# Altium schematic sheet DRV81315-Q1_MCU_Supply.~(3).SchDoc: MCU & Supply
size 431 x 279 mm; Date: Not shown in title block; ApprovedBy: Not shown in title block; CheckedBy: Not shown in title block; Author: Not shown in title block; CompanyName: Not shown in title block; DrawnBy: Mojtaba Afshar; Engineer: Not shown in title block; Organization: Not shown in title block; Address1: Not shown in title block; Address2: Not shown in title block; Address3: Not shown in title block; Address4: Not shown in title block; DocumentNumber: 1; Revision: Use project parameter SCH_Rev; SheetNumber: 1; SheetTotal: 3; PageSetup: Record=PageOptions¦CenterHorizontal=True¦CenterVertical=True¦PrintScale=1.00¦XCorrection=1.00¦YCorrection=1.00¦PrintKind=0¦BorderSize=5000000¦LeftOffset=0¦BottomOffset=0¦Orientation=2¦PaperLength=1000¦PaperWidth=1000¦Scale=100¦PaperSource=15¦PrintQuality=600¦MediaType=1¦DitherType=10¦PaperKind=Letter¦PrintScaleMode=1
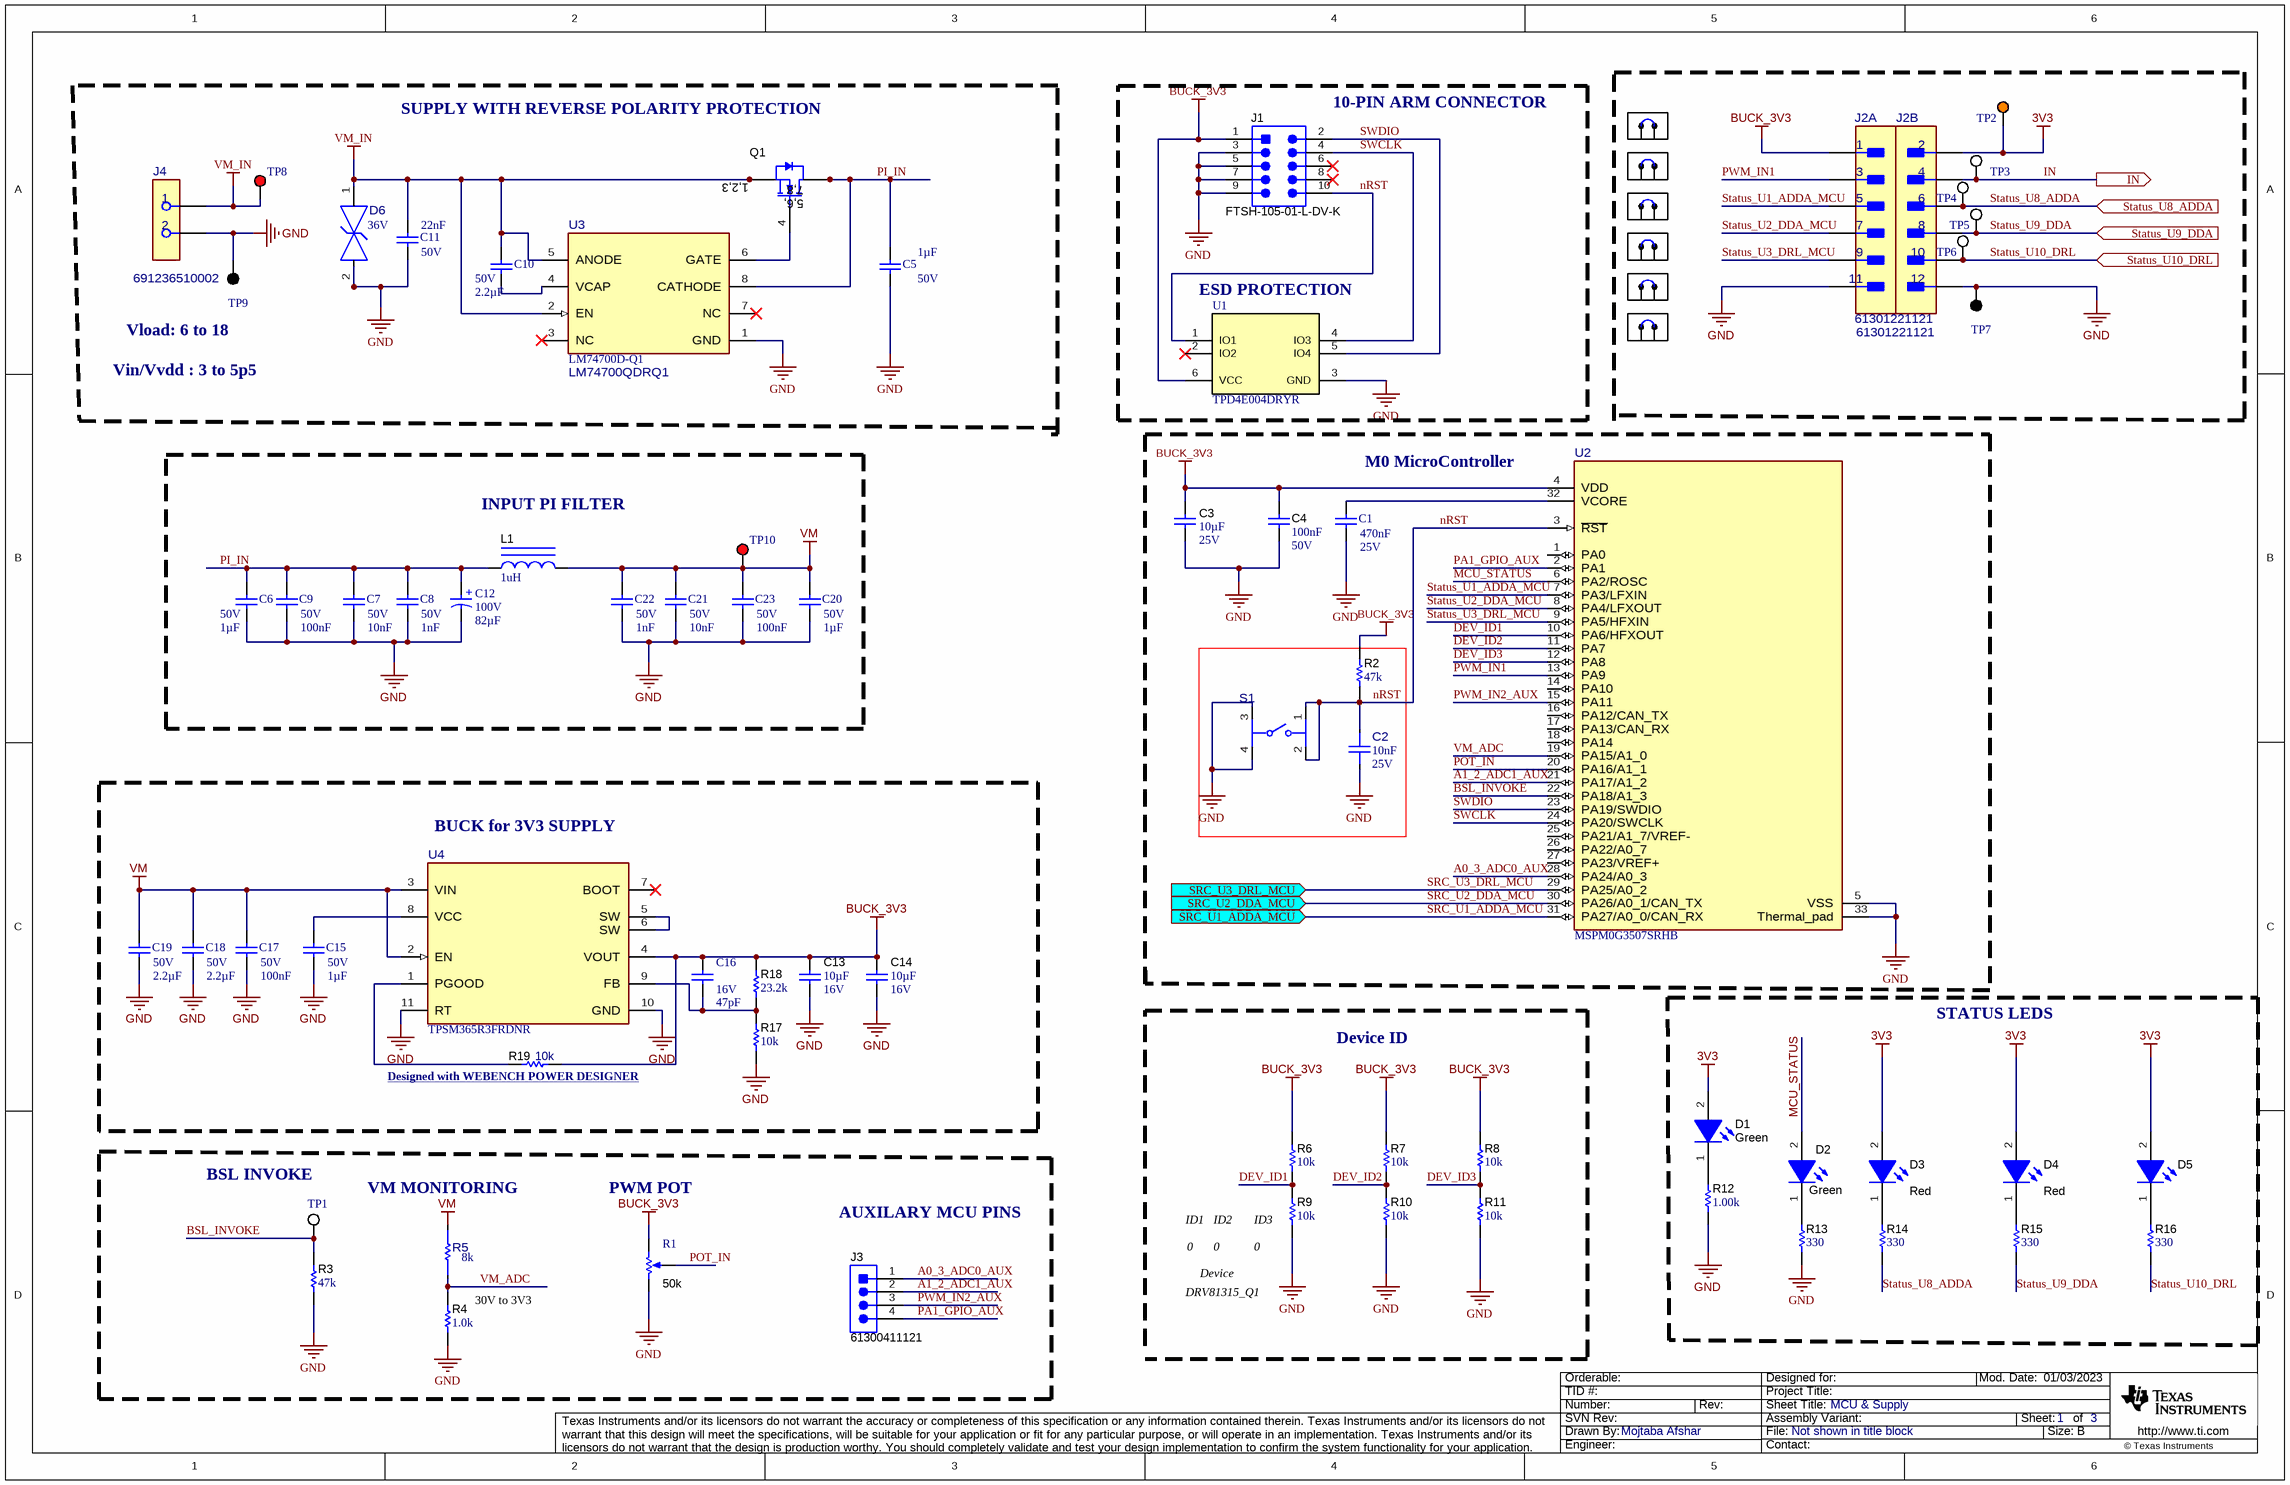
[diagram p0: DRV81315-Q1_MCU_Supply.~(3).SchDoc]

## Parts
C1  value 470nF  Rated Voltage (DC): 25V  [WCAP-CSGP_0603_L1.6W0.8H0.8_Reflow]  (hidden comment: 885012206075R)
C2  Cap_F: 10nF  VDC_V: 25V  [FP-885012206065_0603-MFG]  (hidden comment: 885012206065)
C3  Cap_F: 10µF  VDC_V: 25V  [0603]  (hidden comment: GRM188R61E106KA73D)
C4  Cap_F: 100nF  VDC_V: 50V  [0603]  (hidden comment: 885012206095)
C5  Cap_F: 1µF  Rated Voltage (DC): 50V  [WCAP-CSGP_1206_L3.2W1.6H1.6]  (hidden comment: 885012208093)
C6  Cap_F: 1µF  Rated Voltage (DC): 50V  [WCAP-CSGP_1206_L3.2W1.6H1.6]  (hidden comment: 885012208093)
C7  Cap_F: 10nF  Rated Voltage (DC): 50V  [WCAP-CSGP_0402_L1W0.5H0.5]  (hidden comment: 885012205067)
C8  Cap_F: 1nF  Rated Voltage (DC): 50V  [WCAP-CSGP_0402_L1W0.5H0.5]  (hidden comment: 885012205061)
C9  Cap_F: 100nF  Rated Voltage (DC): 50V  [WCAP-CSGP_0603_L1.6W0.8H0.8_Reflow]  (hidden comment: 885012206095)
C10  Cap_F: 2.2µF  Rated Voltage (DC): 50V  [WCAP-CSGP_1812_L4.5W3.2H2.5]  (hidden comment: 885012210032)
C11  Cap_F: 22nF  Rated Voltage (DC): 50V  [WCAP-CSGP_0603_L1.6W0.8H0.8_Reflow]  (hidden comment: 885012206091)
C12  Cap_F: 82µF  Rated Voltage (DC): 100V  [WCAP-ATUL_D10H20]  (hidden comment: 860040875004)
C13  VDC_V: 16V  ValueDisplayed: 10µF  [0805_150]  (hidden comment: 885012107014)
C14  VDC_V: 16V  ValueDisplayed: 10µF  [0805_150]  (hidden comment: 885012107014)
C15  Cap_F: 1µF  Rated Voltage (DC): 50V  [WCAP-CSGP_1206_L3.2W1.6H1.6]  (hidden comment: 885012208093)
C16  Rated Voltage (DC): 16V  Cap_F: 47pF  [WCAP-CSGP_0402_L1W0.5H0.5]  (hidden comment: 885012005029)
C17  Cap_F: 100nF  Rated Voltage (DC): 50V  [WCAP-CSGP_0603_L1.6W0.8H0.8_Reflow]  (hidden comment: 885012206095)
C18  Cap_F: 2.2µF  Rated Voltage (DC): 50V  [WCAP-CSGP_1812_L4.5W3.2H2.5]  (hidden comment: 885012210032)
C19  Cap_F: 2.2µF  Rated Voltage (DC): 50V  [WCAP-CSGP_1812_L4.5W3.2H2.5]  (hidden comment: 885012210032)
C20  Cap_F: 1µF  Rated Voltage (DC): 50V  [WCAP-CSGP_1206_L3.2W1.6H1.6]  (hidden comment: 885012208093)
C21  Cap_F: 10nF  Rated Voltage (DC): 50V  [WCAP-CSGP_0402_L1W0.5H0.5]  (hidden comment: 885012205067)
C22  Cap_F: 1nF  Rated Voltage (DC): 50V  [WCAP-CSGP_0402_L1W0.5H0.5]  (hidden comment: 885012205061)
C23  Cap_F: 100nF  Rated Voltage (DC): 50V  [WCAP-CSGP_0603_L1.6W0.8H0.8_Reflow]  (hidden comment: 885012206095)
D1  value Green  [WL-SMCW_GREEN]  (hidden comment: 150060VS75000)
D2  value Green  [WL-SMCW_GREEN]  (hidden comment: 150060VS75000)
D3  value Red  [WL-SMCW_RED]  (hidden comment: 150060RS75000)
D4  value Red  [WL-SMCW_RED]  (hidden comment: 150060RS75000)
D5  150060RS75000  [WL-SMCW_RED]  (value not drawn)
D6  VRWM: 36V  [FP-SMBJ36CA-13-F_SMB-MFG]  (hidden comment: SMBJ36CA-13-F)
J1  FTSH-105-01-L-DV-K  [Samtec_FTSH-105-01-x-DV-K]
J2  61301221121  [FP-61301221121_HDR12-MFG]  (parts A,B of 2)
J3  61300411121  [WURTH_61300411121]
J4  691236510002  [FP-691236510002_HHR2-MFG]
L1  ValueDisplayed: 1uH  [WE-LHMI_1335]  (hidden comment: 74437377010)
Q1  CSD19502Q5B  [DNK0008A]  (value not drawn)
R1  value 50k  [Bourns_3352T]  (hidden comment: 3352T-1-503LF)
R2  ValueDisplayed: 47k  [0402]  (hidden comment: CRCW040247K0JNED)
R3  ValueDisplayed: 47k  [0402]  (hidden comment: CRCW040247K0JNED)
R4  ValueDisplayed: 1.0k  [0603]  (hidden comment: RC0603JR-071KL)
R5  value 8k  [FP-RT0603BRE078KL_0603-MFG]  (hidden comment: RT0603BRE078KL)
R6  ValueDisplayed: 10k  [0603L]  (hidden comment: RC0603JR-0710KL)
R7  ValueDisplayed: 10k  [0603L]  (hidden comment: RC0603JR-0710KL)
R8  ValueDisplayed: 10k  [0603L]  (hidden comment: RC0603JR-0710KL)
R9  ValueDisplayed: 10k  [0603L]  (hidden comment: RC0603JR-0710KL)
R10  ValueDisplayed: 10k  [0603L]  (hidden comment: RC0603JR-0710KL)
R11  ValueDisplayed: 10k  [0603L]  (hidden comment: RC0603JR-0710KL)
R12  ValueDisplayed: 1.00k  [0603]  (hidden comment: RC0603FR-071KL)
R13  ValueDisplayed: 330  [0603]  (hidden comment: RC0603JR-07330RL)
R14  ValueDisplayed: 330  [0603]  (hidden comment: RC0603JR-07330RL)
R15  ValueDisplayed: 330  [0603]  (hidden comment: RC0603JR-07330RL)
R16  ValueDisplayed: 330  [0603]  (hidden comment: RC0603JR-07330RL)
R17  ValueDisplayed: 10k  [0603L]  (hidden comment: RC0603JR-0710KL)
R18  ValueDisplayed: 23.2k  [0603]  (hidden comment: RC0603FR-0723K2L)
R19  ValueDisplayed: 10k  [0603L]  (hidden comment: RC0603JR-0710KL)
S1  430481025816  [FP-430481025816_SMT_SW_6MM2_6MM2-MFG]  (value not drawn)
SH1-J2  60900213421  [Wurth_60900213421]  (value not drawn)
SH2-J2  60900213421  [Wurth_60900213421]  (value not drawn)
SH3-J2  60900213421  [Wurth_60900213421]  (value not drawn)
SH4-J2  60900213421  [Wurth_60900213421]  (value not drawn)
SH5-J2  60900213421  [Wurth_60900213421]  (value not drawn)
SH6-J2  60900213421  [Wurth_60900213421]  (value not drawn)
TP1  5002  [Keystone5002]  (value not drawn)
TP2  5013  [Keystone5013]  (value not drawn)
TP3  5012  [Keystone5012]  (value not drawn)
TP4  5012  [Keystone5012]  (value not drawn)
TP5  5012  [Keystone5012]  (value not drawn)
TP6  5012  [Keystone5012]  (value not drawn)
TP7  5011  [Keystone5011]  (value not drawn)
TP8  5010  [Keystone5010]  (value not drawn)
TP9  5011  [Keystone5011]  (value not drawn)
TP10  5010  [Keystone5010]  (value not drawn)
U1  TPD4E004DRYR  [DRY0006A]
U2  MSPM0G3507SRHB  [RHB0032E-MFG]
U3  LM74700QDRQ1  PartNumber: LM74700D-Q1  [D0008A-MFG]
U4  TPSM365R3FRDNR  [RDN0011A-MFG]

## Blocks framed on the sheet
INPUT PI FILTER: C6-C9 C12 C20-C23 L1 TP10
BUCK for 3V3 SUPPLY: C13-C19 R17-R19 U4
STATUS LEDS: D1-D5 R12-R16

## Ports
IN (out), SRC_U1_ADDA_MCU (in), SRC_U2_DDA_MCU (in), SRC_U3_DRL_MCU (in), Status_U8_ADDA (in), Status_U9_DDA (in), Status_U10_DRL (in)

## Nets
3V3: D1.2(A) D3.2(A) D4.2(A) D5.2(A) J2.2 TP2.1
BUCK_3V3: C3.1 C4.1 C13.1 C14.1 C16.2 J1.1 J2.1 R1.1(CCW) R2.2 R6.1 R7.1 R8.1 R18.2 R19.2 U1.6(VCC) U2.4(VDD) U4.4(VOUT)
GND: C1.1 C2.2 C3.2 C4.2 C5.1 C6.1 C7.1 C8.1 C9.1 C11.1 C12.2(N) C13.2 C14.2 C15.1 C17.1 C18.1 C19.1 C20.1 C21.1 C22.1 C23.1 D6.2 J1.3 J1.5 J1.7 J1.9 J2.11 J2.12 J4.2 R1.3(CW) R3.1 R4.1 R9.2 R10.2 R11.2 R12.1 R13.1 R17.1 S1.3 S1.4 TP7.1 TP9.1 U1.3(GND) U2.5(VSS) U2.33(Thermal_pad) U3.1(GND) U4.10(GND) U4.11(RT)
VM: C17.2 C18.2 C19.2 C20.2 C21.2 C22.2 C23.2 L1.2 R5.2 TP10.1 U4.2(EN) U4.3(VIN)
VM_IN: C10.2 C11.2 D6.1 J4.1 Q1.1(S) Q1.2(S) Q1.3(S) TP8.1 U3.2(EN) U3.5(ANODE)
A0_3_ADC0_AUX: J3.1 U2.28(PA24/A0_3)
A1_2_ADC1_AUX: J3.2 U2.21(PA17/A1_2)
BSL_INVOKE: R3.2 TP1.1 U2.22(PA18/A1_3)
DEV_ID1: R6.2 R9.1 U2.10(PA6/HFXOUT)
DEV_ID2: R7.2 R10.1 U2.11(PA7)
DEV_ID3: R8.2 R11.1 U2.12(PA8)
IN: J2.4 TP3.1 ; port IN
MCU_STATUS: D2.2(A) U2.6(PA2/ROSC)
nRST: C2.1 J1.10 R2.1 S1.1 S1.2 U1.1(IO1) U2.3(~{RST})
PA1_GPIO_AUX: J3.4 U2.2(PA1)
PI_IN: C5.2 C6.2 C7.2 C8.2 C9.2 C12.1(P) L1.1 Q1.5(D) Q1.6(D) Q1.7(D) Q1.8(D) Q1.9(D) U3.8(CATHODE)
POT_IN: R1.2(WIPER) U2.20(PA16/A1_1)
PWM_IN1: J2.3 U2.13(PA9)
PWM_IN2_AUX: J3.3 U2.15(PA11)
SRC_U1_ADDA_MCU: U2.31(PA27/A0_0/CAN_RX) ; port SRC_U1_ADDA_MCU
SRC_U2_DDA_MCU: U2.30(PA26/A0_1/CAN_TX) ; port SRC_U2_DDA_MCU
SRC_U3_DRL_MCU: U2.29(PA25/A0_2) ; port SRC_U3_DRL_MCU
Status_U1_ADDA_MCU: J2.5 U2.7(PA3/LFXIN)
Status_U2_DDA_MCU: J2.7 U2.8(PA4/LFXOUT)
Status_U3_DRL_MCU: J2.9 U2.9(PA5/HFXIN)
Status_U8_ADDA: J2.6 R14.1 TP4.1 ; port Status_U8_ADDA
Status_U9_DDA: J2.8 R15.1 TP5.1 ; port Status_U9_DDA
Status_U10_DRL: J2.10 R16.1 TP6.1 ; port Status_U10_DRL
SWCLK: J1.4 U1.4(IO3) U2.24(PA20/SWCLK)
SWDIO: J1.2 U1.5(IO4) U2.23(PA19/SWDIO)
VM_ADC: R4.2 R5.1 U2.19(PA15/A1_0)
NetC1_2: C1.2 U2.32(VCORE)
NetC10_1: C10.1 U3.4(VCAP)
NetC15_2: C15.2 U4.8(VCC)
NetC16_1: C16.1 R17.2 R18.1 U4.9(FB)
NetD1_1: D1.1(K) R12.2
NetD2_1: D2.1(K) R13.2
NetD3_1: D3.1(K) R14.2
NetD4_1: D4.1(K) R15.2
NetD5_1: D5.1(K) R16.2
NetQ1_4: Q1.4(G) U3.6(GATE)
NetR19_1: R19.1 U4.1(PGOOD)
NetU4_5: U4.5(SW) U4.6(SW)

Not connected (* = marked no-connect by the designer): J1 6* 8*; U1 2(IO2)*; U2 1(PA0) 14(PA10) 16(PA12/CAN_TX) 17(PA13/CAN_RX) 18(PA14) 25(PA21/A1_7/VREF-) 26(PA22/A0_7) 27(PA23/VREF+); U3 3(NC)* 7(NC)*; U4 7(BOOT)*

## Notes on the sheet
- SUPPLY WITH REVERSE POLARITY PROTECTION
- (near J1) 10-PIN ARM CONNECTOR
- (near U1) ESD PROTECTION
- (near TP9) Vload: 6 to 18
- Vin/Vvdd : 3 to 5p5
- M0 MicroController
- Device ID
- (near R19) Designed with WEBENCH POWER DESIGNER <https://webench.ti.com/power-designer/switching-regulator/customize/4?VinMin=4.5&VinMax=65&O1V=3.3&O1I=0.3&base_pn=TPSM365R3F&AppType=None&Flavor=None&op_TA=30&origin=pf_panel&lang_chosen=en-US&optfactor=3&Topology=Buck&flavor=None&VoltageOption=None>
- (near TP1) BSL INVOKE
- (near R5) VM MONITORING
- PWM POT
- AUXILARY MCU PINS
- ID1
- ID2
- (near R9) ID3
- 30V to 3V3
- DRV81315_Q1
- 0
- Device
- (near R9) 0

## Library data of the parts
C1 = CMP-0119380-1: WCAP-CSGP Multilayer Ceramic Chip Capacitor, General Purpose, size 0603, X7R Class II, 470nF, 25VDC; Manufacturer: Wurth Elektronik; Capacitance Tolerance: +/-10%; Case/Size Code: 0603; Dissipation Factor: 10%; Insulation Resistance: 1.1GOhm; Technical Reference: X7R0603474K025DFCT20000
C2 = CMP-0120893-1: 10000 pF ±10% 25V Ceramic Capacitor X7R 0603 (1608 Metric); Manufacturer: Wurth Electronics; AEC Qualified: No; SizeZ_mm: 0.87mm; TempCo: 15%; Value: 10nF
C3 = CMP-0860569-1: CAP, CERM, 10 µF, 25 V,+/- 10%, X5R, 0603; Manufacturer: MuRata; TaMin_C: -55°C; Polarized: N; SizeAreaWB_mm2: 4.68; U/M: EA; Value: 10uF; TaMax_C: 85°C; SizeZ_mm: 1; SizeX_mm: 1.6; SizeY_mm: 0.8; SizeArea_mm2: 1.28; AEC Category: Q200
C4 = CMP-0006837-4: CAP, CERM, 0.1 uF, 50 V, +/- 10%, X7R, 0603; Manufacturer: Wurth Elektronik; TaMin_C: -55°C; Polarized: N; SizeAreaWB_mm2: 4.68; Value1: Unknown; U/M: EA; Value: 0.1uF; TaMax_C: 125°C; SizeZ_mm: 1; SizeX_mm: 1.6; SizeY_mm: 0.8; SizeArea_mm2: 1.28; AEC Category: Q200
C5 C6 C15 C20 = CMP-0119636-1: WCAP-CSGP Multilayer Ceramic Chip Capacitor, General Purpose, size 1206, X7R, 1µF, 50VDC; Manufacturer: Wurth Elektronik; Capacitance Tolerance: +/-10%; Case/Size Code: 1206; Dissipation Factor: 3%; Insulation Resistance: 0.5GOhm; Technical Reference: X7R1206105K050DFCT10000
C7 C21 = CMP-0119297-1: WCAP-CSGP Multilayer Ceramic Chip Capacitor, General Purpose, size 0402, X7R, 10nF, 50VDC; Manufacturer: Wurth Elektronik; Capacitance Tolerance: +/-10%; Case/Size Code: 0402; Dissipation Factor: 2.5%; Insulation Resistance: 10GOhm; Technical Reference: X7R0402103K050DFCT10000
C8 C22 = CMP-0119291-1: WCAP-CSGP Multilayer Ceramic Chip Capacitor, General Purpose, size 0402, X7R, 1nF, 50VDC; Manufacturer: Wurth Elektronik; Capacitance Tolerance: +/-10%; Case/Size Code: 0402; Dissipation Factor: 2.5%; Insulation Resistance: 10GOhm; Technical Reference: X7R0402102K050DFCT10000
C9 C17 C23 = CMP-0119402-1: WCAP-CSGP Multilayer Ceramic Chip Capacitor, General Purpose, size 0603, X7R, 100nF, 50VDC; Manufacturer: Wurth Elektronik; Capacitance Tolerance: +/-10%; Case/Size Code: 0603; Dissipation Factor: 3%; Insulation Resistance: 5GOhm; Technical Reference: X7R0603104K050DFCT10000
C10 C18 C19 = CMP-0119739-1: WCAP-CSGP Multilayer Ceramic Chip Capacitor, General Purpose, size 1812, X7R, 2.2µF, 50VDC; Manufacturer: Wurth Elektronik; Capacitance Tolerance: +/-10%; Case/Size Code: 1812; Dissipation Factor: 2.5%; Insulation Resistance: 0.2GOhm; Technical Reference: X7R1812225K050DFCT10000
C11 = CMP-0119398-1: WCAP-CSGP Multilayer Ceramic Chip Capacitor, General Purpose, size 0603, X7R, 22nF, 50VDC; Manufacturer: Wurth Elektronik; Capacitance Tolerance: +/-10%; Case/Size Code: 0603; Dissipation Factor: 2.5%; Insulation Resistance: 10GOhm; Technical Reference: X7R0603223K050DFCT10000
C12 = CMP-0102582-1: WCAP-ATUL Aluminum Electrolytic Capacitor, Radial, THT, D10 x H20mm, 82µF, 100V; Manufacturer: Wurth Elektronik; Capacitance Tolerance: 20%; Dissipation Factor: 9%; Endurance: 7000h; Leakage Current: 82uA; Ripple Current: 600mA; Technical Reference: ATDF200820M100DSPAAG000
C13 C14 = CMP-0078154-1: CAP, CERM, 10 µF, 16 V,+/- 20%, X5R, 0805; Manufacturer: Wurth Elektronik; TaMin_C: -55°C; Polarized: N; SizeAreaWB_mm2: 6.75; U/M: EA; Value: 10uF; TaMax_C: 85°C; SizeZ_mm: 1.5; SizeX_mm: 2; SizeY_mm: 1.25; Cap_Case: 0805; SizeArea_mm2: 2.5; AEC Category: Q200
C16 = CMP-0050226-1: WCAP-CSGP Multilayer Ceramic Chip Capacitor, General Purpose, size 0402, NP0, 47pF, 16VDC; Manufacturer: Wurth Elektronik; Capacitance Tolerance: +/-5%; Insulation Resistance: 10GOhm; Q Factor: 1000; Technical Reference: NP00402470J016DFCT10000; Case/Size Code: 0402
D1 D2 = CMP-0002894-2: LED, Green, SMD; Manufacturer: Wurth Elektronik; Type: AlInGaP; Value2: 2V; Io_A: 20mA; Value1: W
D3-D5 = CMP-0002947-3: LED, Red, SMD; Manufacturer: Wurth Elektronik; Value1: 0.072W; Vf_V: 2V; Angle: 140; Tjmax_C: 85°C; Type: AlInGaP; Vr_V: 5V; Io_A: 30mA; Power_TotalModule: 72mW
D6 = CMP-0098087-1: 58.1V Clamp 10.3A Ipp Tvs Diode Surface Mount SMB; Manufacturer: Diodes Inc; AEC Qualified: No; Standoff Height: 0.05mm; TJmax_C: +150°C; Direction: Bidirectional; Breakdown Voltage: 40V; SizeZ_mm: 2.5mm; Ppk: 600W; Number Of Channels: 1
J1 = CMP-0075634-2: Header(Shrouded), 1.27mm, 5x2, Gold, SMT; Manufacturer: Samtec; Pitch_mm: 1.27; Gender: Male; Cert_CSA: Y; Current_A: 3.3A; Row_Count: 2
J2 = CMP-0092423-1: THT Vertical Pin Header WR-PHD, Pitch 2.54 mm, Dual Row, 12 pins; Manufacturer: Wurth Electronics; Is Female: no; DUT-Pitch_mm: 2.54mm; Row_Count: 2; Current_A: 3A; Voltage_V: 250V; Conn Gender: Male; Conn Orientation: Straight; SizeZ_mm: 8.89mm; ContactFinish: Gold
J3 = CMP-0054798-2: Header, 2.54 mm, 4x1, Gold, TH; Manufacturer: Wurth Elektronik; Pitch_mm: 2.54; Gender: Male; Row_Count: 1; Cert_UL: Y; Shrouded: N
J4 = CMP-0121282-1: 2 Position Wire to Board Terminal Block Horizontal with Board 0.200" (5.08mm) Through Hole; Manufacturer: Wurth Electronics; Current_A: 20A; Row_Count: 1; Voltage_V: 300V; AEC Qualified: No; Conn Gender: Female; Is Female: yes; Max Wire Gauge: 12; Min Wire Gauge: 30; SizeZ_mm: 18.1mm
L1 = CMP-0064132-1: Inductor, Shielded Drum Core, Powdered Iron, 1 uH, 15 A, 0.0027 ohm, SMD; Manufacturer: Wurth Elektronik; Isat: 26A @ 20% inductance drop; Irms: 15A @ 40C rise; Green_Lifecycle: Active; SizeAreaWB_mm2: 226.3; DCR_ohm: 2.7m; Green_REACh: Passed; Value: 1uH; Imax_A: 15A; SizeZ_mm: 3.5; SizeX_mm: 13.5; SizeY_mm: 12.6; SizeArea_mm2: 170.1; Ind_H: 1µH; AEC Category: Q200
Q1 = CMP-0000915-2: MOSFET, N-CH, 80 V, 100 A, DNK0008A (VSON-CLIP-8); Alternate Manufacturer: None; Manufacturer: Texas Instruments; SizeZ_mm: 1; ChType: N; Value2: 48 nC; VdsMax_V: 80V; SizeX_mm: 6; SizeY_mm: 5; Vgs_V: 20V; Value: 80V; SizeArea_mm2: 30; AEC Category: Q101; IdsMax_A: 100A; SizeAreaWB_mm2: 56; U/M: EA; QgTyp_nC: 48
R1 = CMP-0001777-2: Trimming Potentiometer, 50K, 0.5W, TH; Manufacturer: Bourns; CompType: Trimmer
R2 R3 = CMP-0026935-3: RES, 47 k, 5%, 0.063 W, AEC-Q200 Grade 0, 0402; Manufacturer: Vishay-Dale; Power_W: 63mW; TempCo: 200 ppm/C; Value_Code: 47k0; Value: 47k; EIA_Code: E24; SizeX_mm: 1; SizeY_mm: 0.5; SizeZ_mm: 0.6; Value2: 0.063W; AEC Qualified: Y; VDC_V: 50V; AEC Category: Q200; AEC Grade: 0
R4 = CMP-0025899-5: RES, 1.0 k, 5%, 0.1 W, 0603; Manufacturer: Yageo; Power_W: 100mW; TempCo: 100 ppm/C; Value_Code: 1k00; Value: 1.0k; EIA_Code: E24; Res_ohm: 1k; SizeX_mm: 1.6; SizeY_mm: 0.8; SizeZ_mm: 1; Value2: 0.1W; SizeArea_mm2: 1.28; AEC Qualified: N; VDC_V: 75V; AEC Category: Q200; SizeAreaWB_mm2: 4.68
R5 = CMP-0122747-1: 8 kOhms ±0.1% 0.1W, 1/10W Chip Resistor 0603 (1608 Metric) Thin Film; Manufacturer: Yageo; AEC Qualified: No; Power_W: 100mW; SizeZ_mm: 0.55mm; TempCo: 50ppm/°C; VDC_V: 75V
R6-R11 R17 = CMP-0025886-5: RES, 10 k, 5%, 0.1 W, 0603; Manufacturer: Yageo; Power_W: 100mW; TempCo: 100 ppm/C; Value_Code: 10k0; Value: 10k; EIA_Code: E24; SizeX_mm: 1.6; SizeY_mm: 0.8; SizeZ_mm: 1; Value2: 0.1W; SizeArea_mm2: 1.28; AEC Qualified: N; VDC_V: 75V; AEC Category: Q200; SizeAreaWB_mm2: 4.68
R12 = CMP-0022895-5: RES, 1.00 k, 1%, 0.1 W, 0603; Manufacturer: Yageo; Power_W: 100mW; TempCo: 100 ppm/C; Value_Code: 1k00; Value: 1.00k; EIA_Code: E96; Res_ohm: 1k; SizeX_mm: 1.6; SizeY_mm: 0.8; SizeZ_mm: 1; Value2: 0.1W; SizeArea_mm2: 1.28; AEC Qualified: N; VDC_V: 75V; AEC Category: Q200; SizeAreaWB_mm2: 4.68
R13-R16 = CMP-0025912-5: RES, 330, 5%, 0.1 W, 0603; Manufacturer: Yageo; Power_W: 100mW; TempCo: 100 ppm/C; Value_Code: 330R; Value: 330; EIA_Code: E24; SizeX_mm: 1.6; SizeY_mm: 0.8; SizeZ_mm: 1; Value2: 0.1W; SizeArea_mm2: 1.28; AEC Qualified: N; VDC_V: 75V; AEC Category: Q200; SizeAreaWB_mm2: 4.68
R18 = CMP-0022933-5: RES, 23.2 k, 1%, 0.1 W, 0603; Manufacturer: Yageo; Power_W: 100mW; TempCo: 100 ppm/C; Value_Code: 23k2; Value: 23.2k; EIA_Code: E96; SizeX_mm: 1.6; SizeY_mm: 0.8; SizeZ_mm: 1; Value2: 0.1W; SizeArea_mm2: 1.28; AEC Qualified: N; VDC_V: 75V; AEC Category: Q200; SizeAreaWB_mm2: 4.68
R19 = CMP-0025886-3: RES, 10 k, 5%, 0.1 W, 0603; Manufacturer: Yageo; Power_W: 100mW; TempCo: 100 ppm/C; Value_Code: 10k0; U/M: EA; Value: 10k; EIA_Code: E24; SizeX_mm: 1.6; SizeY_mm: 0.8; SizeZ_mm: 1; Value2: 0.1W; SizeArea_mm2: 1.28; VDC_V: 50V; AEC Category: Q200
S1 = CMP-0097347-1: Tactile Switch SPST-NO Top Actuated Surface Mount; Manufacturer: Wurth Electronics; VDC_V: 12V; Electromechanical Life: 1000000Cycles; SizeZ_mm: 2.7mm; Coil Resistance_ohm: 100mΩ; Operating Force: 160gf; AEC Qualified: No; Contact Current Rating: 50mA
SH1-J2 SH2-J2 SH3-J2 SH4-J2 SH5-J2 SH6-J2 = CMP-0003761-2: Shunt, 2.54mm, Gold, Black; Manufacturer: Wurth Elektronik
TP1 = CMP-0055139-2: Test Point, Miniature, White, TH; Manufacturer: Keystone Electronics; ContactFinish: Silver; Green_REACh: Passed; CT: TRUE; Green_Lifecycle: Active; CNHeader: FALSE
TP2 = CMP-0055150-1: Test Point, Multipurpose, Orange, TH; Manufacturer: Keystone; CNHeader: FALSE; Green_Lifecycle: Active; Green_REACh: Passed; ContactFinish: Silver; CT: TRUE
TP3-TP6 = CMP-0055149-2: Test Point, Multipurpose, White, TH; Manufacturer: Keystone Electronics; ContactFinish: Silver; CT: TRUE; CNHeader: FALSE; Green_Lifecycle: Active; Green_REACh: Passed
TP7 = CMP-0055148-2: Test Point, Multipurpose, Black, TH; Manufacturer: Keystone Electronics; CNHeader: FALSE; ContactFinish: Silver; Green_REACh: Passed; Green_Lifecycle: Active; CT: TRUE
TP8 TP10 = CMP-0055147-2: Test Point, Multipurpose, Red, TH; Manufacturer: Keystone Electronics; CNHeader: FALSE; Green_Lifecycle: Active; Green_REACh: Passed; ContactFinish: Silver; CT: TRUE
TP9 = CMP-0055148-2: Test Point, Multipurpose, Black, TH; Manufacturer: Keystone Electronics; CNHeader: FALSE; Green_Lifecycle: Active; Green_REACh: Passed; ContactFinish: Silver; CT: TRUE
U1 = CMP-0043115-2: ESD-Protection Array for High-Speed Data Interfaces, 4 Channels, -40 to +85 degC, 6-pin SON (DRY), Green (RoHS & no Sb/Br); Manufacturer: Texas Instruments; IO Leakage Current(nA): 1; USB High Speed: TRUE; IO Capacitance(Typ)(pF): 1.6; SubFamily: ESD Solution; IEC 61000-4-2 Contact(+/- kV): 8; Breakdown Voltage(Min)(V): 6; IEC 61000-4-2 Air-Gap(+/- kV): 12; AEC Category: Q200; AEC Qualified: N; CompType: IC; SizeAreaWB_mm2: 4.9; SizeArea_mm2: 1.45; SizeX_mm: 1.0; SizeZ_mm: 0.6
U2 = CMP-0093963-1: Mixed-Signal Microcontrollers with CAN-FD Interface, VQFN32; Manufacturer: Texas Instruments; TaMin_C: -40°C; Interface: I2C,SPI,UART,CAN,LIN,IrDA,SMBus; Number Of Cores: 1; Number Of Pwm Channels: 16; Data Bus Width: 32bits; Frequency_Fixed: 80MHz; Core Architecture: ARM Cortex-M0+; Number Of Timers/Counters: 7; Number Of Adc Channels: 10; Number Of Uart Channels: 4; Standoff Height: 0mm; Ram Size: 32KBytes; Number Of A/D Converters: 2; SizeZ_mm: 1mm; AEC Qualified: No; TaMax_C: +125°C; Memory Size: 128KBytes; TJmax_C: +130°C; Min Supply Voltage: 1.62V; Max Supply Voltage: 3.6V; Memory Type: FLASH; Number Of I/Os: 28
U3 = CMP-0125797-1: Manufacturer: Texas Instruments; SizeZ_mm: 1.75mm; Standoff Height: 0.11mm
U4 = CMP-0094617-1: 3-V to 65-V Input, 1-V to 13-V Output, 600-mA Synchronous Buck Converter Power Module in a HotRod QFN Package; Manufacturer: Texas Instruments; SizeZ_mm: 2.1mm; AEC Qualified: No; Max Duty Cycle: 98%; Max Supply Voltage: 65V; Min Supply Voltage: 3.6V; Nominal Supply Current: 17-18uA; Number Of Outputs: 1; Output Type: AdjustableProgrammable; Output Voltage: 1-13V; Standoff Height: 0mm; Switching Frequency: 200-2200kHz; TJmax_C: +125°C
